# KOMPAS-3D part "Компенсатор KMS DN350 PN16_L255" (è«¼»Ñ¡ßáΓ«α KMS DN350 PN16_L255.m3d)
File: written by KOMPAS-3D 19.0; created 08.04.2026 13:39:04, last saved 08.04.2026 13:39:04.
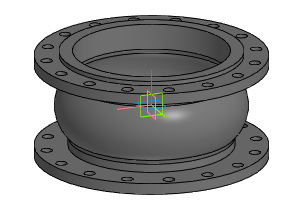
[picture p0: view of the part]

Document properties: Автор: Энергия; Полное имя файла: Z:\3.Личные\kachalov\3d для проектировщиков\7.1 Компенсатор\stp_Компенсатор KSM\Компенсатор KMS DN350 PN16_L255.m3d

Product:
- Part/product: Компенсатор KMS DN350 PN16_L255

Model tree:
1. Операция без истории:1  (labels: Компенсатор KMS DN350 PN16_L255)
